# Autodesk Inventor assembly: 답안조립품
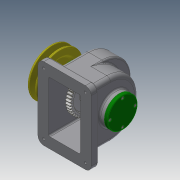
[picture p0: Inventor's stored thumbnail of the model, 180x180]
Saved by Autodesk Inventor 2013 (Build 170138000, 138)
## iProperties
Created: 2017-11
Part Number: 답안조립품
Document SubType Name: Assembly
Designer: Administrator
Author: Administrator
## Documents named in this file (14)
- C:\Users\Administrator\Desktop\471107V1014\답안조립품.iam
- C:\Users\Administrator\Desktop\471107V1014\본체.ipt
- C:\Users\Administrator\Desktop\471107V1014\축.ipt
- C:\Users\Administrator\Desktop\471107V1014\앞커버.ipt
- C:\Users\Administrator\Desktop\471107V1014\뒤커버.ipt
- C:\Users\Administrator\Desktop\471107V1014\스퍼기어.ipt
- C:\Users\Administrator\Desktop\471107V1014\볼트 M3 x 8.ipt
- C:\Users\Administrator\Desktop\471107V1014\키 - 6 x 6 x 22.ipt
- C:\Users\Administrator\Desktop\471107V1014\키 - 5 x 5 x 18.ipt
- C:\Users\Administrator\Desktop\471107V1014\멈춤나사 - M4 x 10.ipt
- 멈춤나사 - M4 x 10.ipt
- C:\Users\Administrator\Desktop\471107V1014\V-벨트풀리.ipt
- C:\Users\Administrator\Desktop\471107V1014\베어링 6002.ipt
- C:\Users\Administrator\Desktop\471107V1014\오일 실 15 30 7.ipt
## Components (1 placed, 1 different names)
1. V-벨트풀리:1
